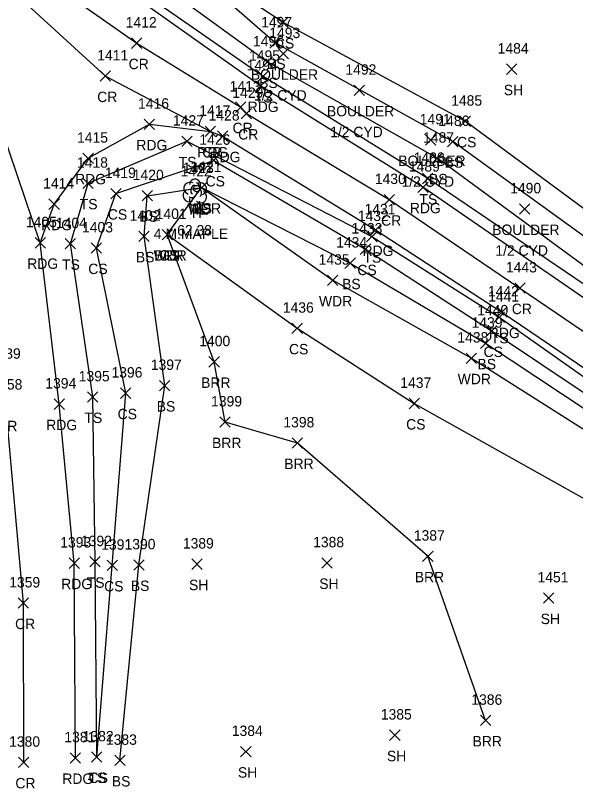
# Model space of a CAD drawing. Extents: x 1469310 to 1475157, y 493997 to 498873.
# Drawn here: x 1469633 to 1469740.5, y 498328.3 to 498476.8 of the extents above; entities that cross this region are included whole.
import ezdxf

# ---------------------------------------------------------------- set-up
doc = ezdxf.new("R2010")
doc.units = 0
for name, color, linetype in [('C_A', 7, 'Continuous'), ('C_C', 7, 'Continuous'), ('C_I', 7, 'Continuous'), ('CBP', 7, 'Continuous'), ('L_A', 7, 'Continuous'), ('L_C', 7, 'Continuous'), ('L_I', 7, 'Continuous'), ('L_TIC', 7, 'Continuous'), ('LABL', 7, 'Continuous'), ('LAWA', 7, 'Continuous'), ('LELB', 7, 'Continuous'), ('LTD', 7, 'Continuous'), ('P_A', 7, 'Continuous'), ('P_I', 7, 'Continuous'), ('P_TIC', 7, 'Continuous'), ('PEU', 7, 'Continuous'), ('PRC', 7, 'Continuous')]:
    doc.layers.add(name, color=color, linetype=linetype)

msp = doc.modelspace()

# ---------------------------------------------------------------- linework, layer by layer
at = {"layer": 'CBP'}
for radius in [0.625, 0.0833]:
    msp.add_circle((1469667.8, 498443.5), radius, dxfattribs=at)
at = {"layer": 'L_TIC'}
for points in [[(1469683.35, 498474.42), (1469685.35, 498476.42)], [(1469685.35, 498474.42), (1469683.35, 498476.42)], [(1469681.84, 498470.48), (1469683.84, 498472.48)], [(1469683.84, 498470.48), (1469681.84, 498472.48)], [(1469683.41, 498468.41), (1469685.41, 498470.41)], [(1469685.41, 498468.41), (1469683.41, 498470.41)], [(1469680.33, 498466.82), (1469682.33, 498468.82)], [(1469682.33, 498466.82), (1469680.33, 498468.82)], [(1469727.27, 498465.44), (1469729.27, 498467.44)], [(1469729.27, 498465.44), (1469727.27, 498467.44)], [(1469679.51, 498464.06), (1469681.51, 498466.06)], [(1469681.51, 498464.06), (1469679.51, 498466.06)], [(1469698.03, 498461.38), (1469700.03, 498463.38)], [(1469700.03, 498461.38), (1469698.03, 498463.38)], [(1469718.33, 498455.43), (1469720.33, 498457.43)], [(1469720.33, 498455.43), (1469718.33, 498457.43)], [(1469664.9, 498451.6), (1469666.9, 498453.6)], [(1469666.9, 498451.6), (1469664.9, 498453.6)], [(1469711.73, 498451.85), (1469713.73, 498453.85)], [(1469713.73, 498451.85), (1469711.73, 498453.85)], [(1469715.94, 498451.54), (1469717.94, 498453.54)], [(1469717.94, 498451.54), (1469715.94, 498453.54)], [(1469670.04, 498447.92), (1469672.04, 498449.92)], [(1469672.04, 498447.92), (1469670.04, 498449.92)], [(1469712.94, 498448.33), (1469714.94, 498450.33)], [(1469714.94, 498448.33), (1469712.94, 498450.33)], [(1469645.9, 498443.52), (1469647.9, 498445.52)], [(1469647.9, 498443.52), (1469645.9, 498445.52)], [(1469711.15, 498444.44), (1469713.15, 498446.44)], [(1469713.15, 498444.44), (1469711.15, 498446.44)], [(1469667.7, 498442.7), (1469669.7, 498444.7)], [(1469669.7, 498442.7), (1469667.7, 498444.7)], [(1469667.7, 498442.7), (1469669.7, 498444.7)], [(1469669.7, 498442.7), (1469667.7, 498444.7)], [(1469651.26, 498441.54), (1469653.26, 498443.54)], [(1469653.26, 498441.54), (1469651.26, 498443.54)], [(1469657.27, 498441.14), (1469659.27, 498443.14)], [(1469659.27, 498441.14), (1469657.27, 498443.14)], [(1469729.76, 498438.6), (1469731.76, 498440.6)], [(1469731.76, 498438.6), (1469729.76, 498440.6)], [(1469656.65, 498433.35), (1469658.65, 498435.35)], [(1469658.65, 498433.35), (1469656.65, 498435.35)], [(1469661.11, 498433.67), (1469663.11, 498435.67)], [(1469663.11, 498433.67), (1469661.11, 498435.67)], [(1469661.11, 498433.67), (1469663.11, 498435.67)], [(1469663.11, 498433.67), (1469661.11, 498435.67)], [(1469661.11, 498433.67), (1469663.11, 498435.67)], [(1469663.11, 498433.67), (1469661.11, 498435.67)], [(1469700.4, 498433.28), (1469702.4, 498435.28)], [(1469702.4, 498433.28), (1469700.4, 498435.28)], [(1469642.5, 498431.91), (1469644.5, 498433.91)], [(1469644.5, 498431.91), (1469642.5, 498433.91)], [(1469647.51, 498431.09), (1469649.51, 498433.09)], [(1469649.51, 498431.09), (1469647.51, 498433.09)], [(1469699.19, 498430.88), (1469701.19, 498432.88)], [(1469701.19, 498430.88), (1469699.19, 498432.88)], [(1469696.25, 498428.19), (1469698.25, 498430.19)], [(1469698.25, 498428.19), (1469696.25, 498430.19)], [(1469692.89, 498424.89), (1469694.89, 498426.89)], [(1469694.89, 498424.89), (1469692.89, 498426.89)], [(1469724.86, 498417.8), (1469726.86, 498419.8)], [(1469726.86, 498417.8), (1469724.86, 498419.8)], [(1469686.06, 498415.67), (1469688.06, 498417.67)], [(1469688.06, 498415.67), (1469686.06, 498417.67)], [(1469723.42, 498415.16), (1469725.42, 498417.16)], [(1469725.42, 498415.16), (1469723.42, 498417.16)], [(1469722.26, 498412.8), (1469724.26, 498414.8)], [(1469724.26, 498412.8), (1469722.26, 498414.8)], [(1469670.12, 498409.23), (1469672.12, 498411.23)], [(1469672.12, 498409.23), (1469670.12, 498411.23)], [(1469719.54, 498409.93), (1469721.54, 498411.93)], [(1469721.54, 498409.93), (1469719.54, 498411.93)], [(1469660.64, 498404.68), (1469662.64, 498406.68)], [(1469662.64, 498404.68), (1469660.64, 498406.68)], [(1469653.15, 498403.21), (1469655.15, 498405.21)], [(1469655.15, 498403.21), (1469653.15, 498405.21)], [(1469646.81, 498402.48), (1469648.81, 498404.48)], [(1469648.81, 498402.48), (1469646.81, 498404.48)], [(1469708.56, 498401.23), (1469710.56, 498403.23)], [(1469710.56, 498401.23), (1469708.56, 498403.23)], [(1469672.23, 498397.66), (1469674.23, 498399.66)], [(1469674.23, 498397.66), (1469672.23, 498399.66)], [(1469686.11, 498393.64), (1469688.11, 498395.64)], [(1469688.11, 498393.64), (1469686.11, 498395.64)], [(1469711.16, 498371.9), (1469713.16, 498373.9)], [(1469713.16, 498371.9), (1469711.16, 498373.9)], [(1469647.24, 498370.84), (1469649.24, 498372.84)], [(1469649.24, 498370.84), (1469647.24, 498372.84)], [(1469666.81, 498370.38), (1469668.81, 498372.38)], [(1469668.81, 498370.38), (1469666.81, 498372.38)], [(1469691.82, 498370.62), (1469693.82, 498372.62)], [(1469693.82, 498370.62), (1469691.82, 498372.62)], [(1469650.55, 498370.14), (1469652.55, 498372.14)], [(1469652.55, 498370.14), (1469650.55, 498372.14)], [(1469655.67, 498370.22), (1469657.67, 498372.22)], [(1469657.67, 498370.22), (1469655.67, 498372.22)], [(1469734.35, 498363.87), (1469736.35, 498365.87)], [(1469736.35, 498363.87), (1469734.35, 498365.87)], [(1469722.26, 498340.37), (1469724.26, 498342.37)], [(1469724.26, 498340.37), (1469722.26, 498342.37)], [(1469704.82, 498337.53), (1469706.82, 498339.53)], [(1469706.82, 498337.53), (1469704.82, 498339.53)], [(1469647.57, 498333.34), (1469649.57, 498335.34)], [(1469649.57, 498333.34), (1469647.57, 498335.34)], [(1469647.57, 498333.34), (1469649.57, 498335.34)], [(1469649.57, 498333.34), (1469647.57, 498335.34)], [(1469676.2, 498334.38), (1469678.2, 498336.38)], [(1469678.2, 498334.38), (1469676.2, 498336.38)], [(1469652.02, 498332.68), (1469654.02, 498334.68)], [(1469654.02, 498332.68), (1469652.02, 498334.68)]]:
    msp.add_lwpolyline(points, dxfattribs=at)
at = {"layer": 'LABL'}
msp.add_lwpolyline([(1469723.26, 498341.37), (1469712.16, 498372.9), (1469687.11, 498394.64), (1469673.23, 498398.66), (1469671.12, 498410.23), (1469662.11, 498434.67)], dxfattribs=at)
at = {"layer": 'LAWA'}
msp.add_lwpolyline([(1469662.11, 498434.67), (1469668.7, 498443.7), (1469693.89, 498425.89), (1469720.54, 498410.93), (1469750.75, 498391.77), (1469774.73, 498375.55)], dxfattribs=at)
at = {"layer": 'LELB'}
for points in [[(1469788.82, 498394.72), (1469772.49, 498406.1), (1469747.63, 498424.65), (1469713.94, 498449.33), (1469681.33, 498467.82), (1469654.97, 498486.97), (1469638.09, 498508.74), (1469624.13, 498529.31), (1469618.93, 498538.23), (1469619.74, 498548.83)], [(1469787.64, 498392.56), (1469771.33, 498404.28), (1469746.15, 498422.39), (1469712.15, 498445.44), (1469680.51, 498465.06), (1469652.75, 498484.35), (1469633.1, 498503.6), (1469618.23, 498526.44), (1469608.67, 498544.39), (1469612.83, 498546.46)], [(1469794.77, 498402.66), (1469777.73, 498412.13), (1469751.37, 498432.82), (1469719.33, 498456.43), (1469684.35, 498475.42), (1469659.61, 498491.8), (1469644.94, 498514.45), (1469661.82, 498527.77), (1469668.13, 498535.82)], [(1469791.56, 498399.11), (1469776.42, 498410.49), (1469750.48, 498428.3), (1469716.94, 498452.54), (1469682.84, 498471.48), (1469659.61, 498491.8)], [(1469648.57, 498334.34), (1469648.24, 498371.84), (1469647.81, 498403.48), (1469643.5, 498432.91), (1469646.9, 498444.52), (1469665.9, 498452.6), (1469701.4, 498434.28), (1469725.86, 498418.8), (1469754.46, 498398.63), (1469779.96, 498380.44)], [(1469648.57, 498334.34), (1469651.55, 498371.14), (1469654.15, 498404.21), (1469648.51, 498432.09), (1469652.26, 498442.54), (1469671.04, 498448.92), (1469700.19, 498431.88), (1469724.42, 498416.16), (1469753.19, 498396.92), (1469778.45, 498378.59)], [(1469653.02, 498333.68), (1469656.67, 498371.22), (1469661.64, 498405.68), (1469657.65, 498434.35), (1469658.27, 498442.14), (1469668.7, 498443.7), (1469697.25, 498429.19), (1469723.26, 498413.8), (1469752.21, 498394.61), (1469776.09, 498376.91)], [(1469662.11, 498434.67), (1469687.06, 498416.67), (1469709.56, 498402.23), (1469745.48, 498382.12), (1469762.96, 498369.88)]]:
    msp.add_lwpolyline(points, dxfattribs=at)
at = {"layer": 'LTD'}
msp.add_line((1469667.39, 498442.84), (1469667.39, 498442.84), dxfattribs=at)
msp.add_line((1469667.39, 498442.84), (1469667.39, 498442.84), dxfattribs=at)
msp.add_arc((1469667.44, 498444.28), 1.05, 335.5272, 180.9563, dxfattribs=at)
for centre, major_axis, ratio, start_param, end_param in [((1469666.6, 498443.51), (1.21, -0.51), 0.895232, 1.570796, 4.712389), ((1469667.18, 498443.3), (-0.208, -0.792), 0.645439, 3.141593, 6.283185), ((1469668.43, 498443.43), (-1.14, -0.48), 0.949671, 1.570796, 4.712389), ((1469666.31, 498442.14), (0.58, -1.04), 0.959034, 3.141593, 6.283185), ((1469666.93, 498442.09), (-0.625, -0.083), 0.423636, 0, 3.141593), ((1469667.89, 498442.68), (-0.5, 0.667), 0.989748, 3.141593, 6.283185), ((1469668.39, 498442.01), (-1.09, 0.79), 0.841452, 1.570796, 4.712389), ((1469667.39, 498441.34), (0.26, 1.06), 0.942809, 1.570796, 4.712389)]:
    msp.add_ellipse(centre, major_axis=major_axis, ratio=ratio, start_param=start_param, end_param=end_param, dxfattribs=at)
at = {"layer": 'P_TIC'}
for points in [[(1469655.26, 498470.44), (1469657.26, 498472.44)], [(1469657.26, 498470.44), (1469655.26, 498472.44)], [(1469649.23, 498464.12), (1469651.23, 498466.12)], [(1469651.23, 498464.12), (1469649.23, 498466.12)], [(1469679.07, 498462.21), (1469681.07, 498464.21)], [(1469681.07, 498462.21), (1469679.07, 498464.21)], [(1469675.23, 498458.15), (1469677.23, 498460.15)], [(1469677.23, 498458.15), (1469675.23, 498460.15)], [(1469676.31, 498456.92), (1469678.31, 498458.92)], [(1469678.31, 498456.92), (1469676.31, 498458.92)], [(1469657.69, 498454.86), (1469659.69, 498456.86)], [(1469659.69, 498454.86), (1469657.69, 498456.86)], [(1469669.4, 498453.48), (1469671.4, 498455.48)], [(1469671.4, 498453.48), (1469669.4, 498455.48)], [(1469669.4, 498453.48), (1469671.4, 498455.48)], [(1469671.4, 498453.48), (1469669.4, 498455.48)], [(1469671.75, 498452.58), (1469673.75, 498454.58)], [(1469673.75, 498452.58), (1469671.75, 498454.58)], [(1469645.92, 498448.33), (1469647.92, 498450.33)], [(1469647.92, 498448.33), (1469645.92, 498450.33)], [(1469710.23, 498442.77), (1469712.23, 498444.77)], [(1469712.23, 498442.77), (1469710.23, 498444.77)], [(1469703.76, 498440.38), (1469705.76, 498442.38)], [(1469705.76, 498440.38), (1469703.76, 498442.38)], [(1469639.39, 498439.51), (1469641.39, 498441.51)], [(1469641.39, 498439.51), (1469639.39, 498441.51)], [(1469701.13, 498434.56), (1469703.13, 498436.56)], [(1469703.13, 498434.56), (1469701.13, 498436.56)], [(1469636.73, 498432.09), (1469638.73, 498434.09)], [(1469638.73, 498432.09), (1469636.73, 498434.09)], [(1469636.73, 498432.09), (1469638.73, 498434.09)], [(1469638.73, 498432.09), (1469636.73, 498434.09)], [(1469728.86, 498423.4), (1469730.86, 498425.4)], [(1469730.86, 498423.4), (1469728.86, 498425.4)], [(1469725.39, 498418.79), (1469727.39, 498420.79)], [(1469727.39, 498418.79), (1469725.39, 498420.79)], [(1469640.38, 498401.11), (1469642.38, 498403.11)], [(1469642.38, 498401.11), (1469640.38, 498403.11)], [(1469643.25, 498370.57), (1469645.25, 498372.57)], [(1469645.25, 498370.57), (1469643.25, 498372.57)], [(1469633.46, 498362.9), (1469635.46, 498364.9)], [(1469635.46, 498362.9), (1469633.46, 498364.9)], [(1469633.52, 498332.31), (1469635.52, 498334.31)], [(1469635.52, 498332.31), (1469633.52, 498334.31)], [(1469643.47, 498333.17), (1469645.47, 498335.17)], [(1469645.47, 498333.17), (1469643.47, 498335.17)]]:
    msp.add_lwpolyline(points, dxfattribs=at)
at = {"layer": 'PEU'}
for points in [[(1469787.29, 498391.19), (1469770.79, 498403.19), (1469744.94, 498420.51), (1469711.23, 498443.77), (1469680.07, 498463.21), (1469651.58, 498483.41), (1469630.63, 498501.52), (1469612.52, 498523.24), (1469599.41, 498542.19), (1469591.57, 498556.6), (1469575.61, 498583.06), (1469557.31, 498607.49), (1469540.09, 498628.65), (1469536.24, 498634.99), (1469514.98, 498658.51), (1469490.83, 498684.27), (1469472.69, 498702.57), (1469444.89, 498732.16), (1469424.97, 498753.74), (1469411.28, 498767.74), (1469386.83, 498794.07), (1469360.47, 498820.44)], [(1469637.73, 498433.09), (1469628.78, 498459.19), (1469619.32, 498491.12), (1469611.93, 498509.33), (1469599.41, 498542.19)], [(1469644.47, 498334.17), (1469644.25, 498371.57), (1469641.38, 498402.11), (1469637.73, 498433.09), (1469640.39, 498440.51), (1469646.92, 498449.33), (1469658.69, 498455.86), (1469670.4, 498454.48), (1469672.75, 498453.58), (1469702.13, 498435.56), (1469726.39, 498419.79), (1469755.45, 498400.08), (1469781.34, 498382.02)]]:
    msp.add_lwpolyline(points, dxfattribs=at)
at = {"layer": 'PRC'}
for points in [[(1469423.49, 498741.59), (1469452.57, 498710.45), (1469477.96, 498685.46), (1469512.01, 498647.6), (1469532.7, 498623.32), (1469554.78, 498596.5), (1469570.66, 498571.79), (1469585.25, 498547.18), (1469603.31, 498509.95), (1469610.7, 498488.94), (1469623.7, 498439.14), (1469630.72, 498407.83), (1469631.04, 498401.91), (1469634.46, 498363.9), (1469634.52, 498333.31)], [(1469611.93, 498509.33), (1469635.59, 498485.96), (1469656.26, 498471.44), (1469676.23, 498459.15), (1469677.31, 498457.92), (1469704.76, 498441.38), (1469729.86, 498424.4), (1469757.53, 498405.58), (1469784.33, 498386.63)], [(1469631.71, 498482.13), (1469650.23, 498465.12), (1469670.4, 498454.48)]]:
    msp.add_lwpolyline(points, dxfattribs=at)

# ---------------------------------------------------------------- texts
at = {"layer": 'C_A'}
msp.add_text('TIE', height=2, dxfattribs=at).set_placement((1469665.88, 498438.5))
at = {"layer": 'C_C'}
msp.add_text('62.38', height=2, dxfattribs=at).set_placement((1469664.01, 498434.5))
at = {"layer": 'C_I'}
msp.add_text('1423', height=2, dxfattribs=at).set_placement((1469665.11, 498446.5))
at = {"layer": 'L_A'}
for s, p in [('CS', (1469682.79, 498470.42)), ('BS', (1469681.28, 498466.48)), ('BOULDER', (1469678.16, 498464.41)), ('BS', (1469679.77, 498462.82)), ('SH', (1469726.75, 498461.44)), ('TS', (1469678.92, 498460.06)), ('BOULDER', (1469692.78, 498457.38)), ('CS', (1469717.77, 498451.43)), ('TS', (1469664.31, 498447.6)), ('BOULDER', (1469706.49, 498447.85)), ('BS', (1469715.38, 498447.54)), ('CS', (1469669.48, 498443.92)), ('BS', (1469712.39, 498444.33)), ('TS', (1469710.56, 498440.44)), ('TS', (1469645.31, 498439.52)), ('WDR', (1469666.06, 498438.7)), ('BS', (1469667.14, 498438.7)), ('CS', (1469650.7, 498437.54)), ('H', (1469666.83, 498437.84)), ('BS', (1469656.71, 498437.14)), ('BOULDER', (1469724.52, 498434.6)), ('BS', (1469656.09, 498429.35)), ('WDR', (1469659.47, 498429.67)), ('BRR', (1469659.6, 498429.67)), ('CS', (1469660.55, 498429.67)), ('TS', (1469699.81, 498429.28)), ('TS', (1469641.91, 498427.91)), ('CS', (1469646.95, 498427.09)), ('CS', (1469698.63, 498426.88)), ('BS', (1469695.69, 498424.19)), ('WDR', (1469691.25, 498420.89)), ('TS', (1469724.27, 498413.8)), ('CS', (1469685.5, 498411.67)), ('CS', (1469722.87, 498411.16)), ('BS', (1469721.7, 498408.8)), ('BRR', (1469668.61, 498405.23)), ('WDR', (1469717.9, 498405.93)), ('BS', (1469660.09, 498400.68)), ('CS', (1469652.59, 498399.21)), ('TS', (1469646.22, 498398.48)), ('CS', (1469708, 498397.23)), ('BRR', (1469670.72, 498393.66)), ('BRR', (1469684.59, 498389.64)), ('BRR', (1469709.65, 498367.9)), ('TS', (1469646.65, 498366.84)), ('CS', (1469649.99, 498366.14)), ('BS', (1469655.12, 498366.22)), ('SH', (1469666.3, 498366.38)), ('SH', (1469691.31, 498366.62)), ('SH', (1469733.84, 498359.87)), ('BRR', (1469720.75, 498336.37)), ('SH', (1469704.31, 498333.53)), ('SH', (1469675.69, 498330.38)), ('TS', (1469646.98, 498329.34)), ('CS', (1469647.01, 498329.34)), ('BS', (1469651.46, 498328.68))]:
    msp.add_text(s, height=2, dxfattribs=at).set_placement(p)
at = {"layer": 'L_C'}
for s, p in [('1/2 CYD', (1469678.78, 498460.41)), ('1/2 CYD', (1469693.4, 498453.38)), ('1/2 CYD', (1469707.1, 498443.85)), ('4 M.MAPLE', (1469659.53, 498433.84)), ('1/2 CYD', (1469725.13, 498430.6))]:
    msp.add_text(s, height=2, dxfattribs=at).set_placement(p)
at = {"layer": 'L_I'}
for s, p in [('1497', (1469680.15, 498474.48)), ('1493', (1469681.71, 498472.41)), ('1496', (1469678.58, 498470.82)), ('1484', (1469725.57, 498469.44)), ('1495', (1469677.82, 498468.06)), ('1492', (1469696.33, 498465.38)), ('1485', (1469716.64, 498459.43)), ('1427', (1469663.2, 498455.6)), ('1491', (1469710.61, 498455.85)), ('1486', (1469714.19, 498455.54)), ('1487', (1469711.25, 498452.33)), ('1426', (1469668.29, 498451.92)), ('1488', (1469709.46, 498448.44)), ('1418', (1469644.77, 498447.52)), ('1421', (1469666.57, 498446.7)), ('1421', (1469666.57, 498446.7)), ('1419', (1469650.13, 498445.54)), ('1420', (1469655.49, 498445.14)), ('1422', (1469664.7, 498445.84)), ('1490', (1469727.98, 498442.6)), ('1402', (1469654.88, 498437.35)), ('1401', (1469659.9, 498437.67)), ('1401', (1469659.9, 498437.67)), ('1401', (1469659.9, 498437.67)), ('1432', (1469698.71, 498437.28)), ('1404', (1469640.73, 498435.91)), ('1403', (1469645.74, 498435.09)), ('1433', (1469697.49, 498434.88)), ('1434', (1469694.55, 498432.19)), ('1435', (1469691.19, 498428.89)), ('1441', (1469723.74, 498421.8)), ('1436', (1469684.31, 498419.67)), ('1440', (1469721.65, 498419.16)), ('1439', (1469720.56, 498416.8)), ('1438', (1469717.84, 498413.93)), ('1400', (1469668.26, 498413.23)), ('1397', (1469658.95, 498408.68)), ('1395', (1469645.11, 498406.48)), ('1396', (1469651.4, 498407.21)), ('1437', (1469706.87, 498405.23)), ('1399', (1469670.53, 498401.66)), ('1398', (1469684.41, 498397.64)), ('1392', (1469645.54, 498374.84)), ('1387', (1469709.47, 498375.9)), ('1391', (1469649.43, 498374.14)), ('1390', (1469653.9, 498374.22)), ('1389', (1469665.11, 498374.38)), ('1388', (1469690.13, 498374.62)), ('1451', (1469733.22, 498367.87)), ('1386', (1469720.51, 498344.37)), ('1385', (1469703.13, 498341.53)), ('1384', (1469674.51, 498338.38)), ('1382', (1469645.87, 498337.34)), ('1382', (1469645.87, 498337.34)), ('1383', (1469650.33, 498336.68))]:
    msp.add_text(s, height=2, dxfattribs=at).set_placement(p)
at = {"layer": 'P_A'}
for s, p in [('CR', (1469654.7, 498466.44)), ('CR', (1469648.66, 498460.12)), ('RDG', (1469677.56, 498458.21)), ('CR', (1469674.66, 498454.15)), ('CR', (1469675.74, 498452.92)), ('RDG', (1469656.18, 498450.86)), ('RDG', (1469667.89, 498449.48)), ('CR', (1469668.83, 498449.48)), ('RDG', (1469670.24, 498448.58)), ('RDG', (1469644.41, 498444.33)), ('RDG', (1469708.71, 498438.77)), ('CR', (1469703.19, 498436.38)), ('RDG', (1469637.88, 498435.51)), ('RDG', (1469699.62, 498430.56)), ('RDG', (1469635.22, 498428.09)), ('RDG', (1469635.22, 498428.09)), ('CR', (1469728.29, 498419.4)), ('RDG', (1469723.87, 498414.79)), ('RDG', (1469638.87, 498397.11)), ('CR', (1469629.47, 498396.91)), ('RDG', (1469641.74, 498366.57)), ('CR', (1469632.89, 498358.9)), ('RDG', (1469641.96, 498329.17)), ('CR', (1469632.95, 498328.31))]:
    msp.add_text(s, height=2, dxfattribs=at).set_placement(p)
at = {"layer": 'P_I'}
for s, p in [('1412', (1469654.14, 498474.44)), ('1411', (1469648.67, 498468.12)), ('1494', (1469677.38, 498466.21)), ('1413', (1469674.1, 498462.15)), ('1429', (1469674.61, 498460.92)), ('1416', (1469656.51, 498458.86)), ('1417', (1469668.27, 498457.48)), ('1417', (1469668.27, 498457.48)), ('1428', (1469670.06, 498456.58)), ('1415', (1469644.79, 498452.33)), ('1489', (1469708.52, 498446.77)), ('1414', (1469638.27, 498443.51)), ('1430', (1469701.98, 498444.38)), ('1431', (1469700, 498438.56)), ('1405', (1469634.96, 498436.09)), ('1405', (1469634.96, 498436.09)), ('1443', (1469727.16, 498427.4)), ('1442', (1469723.69, 498422.79)), ('1339', (1469628.02, 498410.83)), ('1358', (1469628.34, 498404.91)), ('1394', (1469638.69, 498405.11)), ('1393', (1469641.56, 498374.57)), ('1359', (1469631.76, 498366.9)), ('1380', (1469631.74, 498336.31)), ('1381', (1469642.35, 498337.17))]:
    msp.add_text(s, height=2, dxfattribs=at).set_placement(p)

doc.saveas('drawing.dxf')
